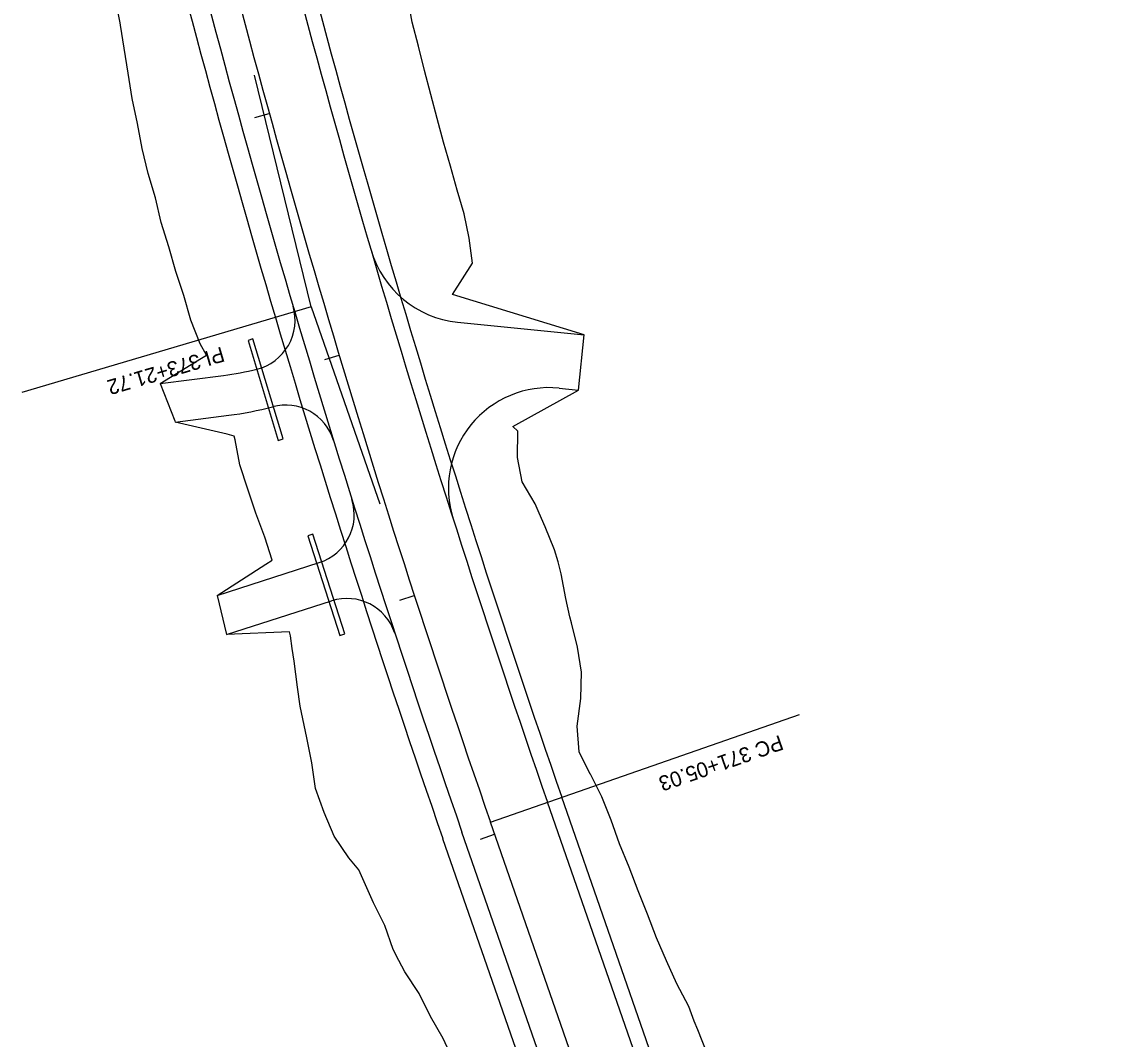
# Model space of a CAD drawing. Extents: x 948761 to 996004, y 1858548 to 1925175.
# Drawn here: x 960783.3 to 961214.2, y 1907979.6 to 1908383.8 of the extents above; entities that cross this region are included whole.
import ezdxf

# ---------------------------------------------------------------- set-up
doc = ezdxf.new("R2010")
doc.units = 0
for name, color, linetype in [('R_Drainage', 7, 'Continuous'), ('R_Horz Alg', 7, 'Continuous'), ('R_Horz Alg Annot', 7, 'Continuous'), ('R_Proposed Const Limits', 7, 'Continuous'), ('R_Proposed Road', 7, 'Continuous')]:
    doc.layers.add(name, color=color, linetype=linetype)

msp = doc.modelspace()

# ---------------------------------------------------------------- linework, layer by layer
at = {"layer": 'R_Drainage'}
for p, q in [((960875.16, 1908257.78), (960873.24, 1908257.2)), ((960887.15, 1908218.06), (960875.16, 1908257.78)), ((960873.24, 1908257.2), (960885.23, 1908217.49)), ((960885.23, 1908217.49), (960887.15, 1908218.06)), ((960898.93, 1908180.24), (960897.03, 1908179.63)), ((960911.66, 1908140.62), (960898.93, 1908180.24)), ((960897.03, 1908179.63), (960909.75, 1908140)), ((960909.75, 1908140), (960911.66, 1908140.62))]:
    msp.add_line(p, q, dxfattribs=at)
at = {"layer": 'R_Horz Alg'}
msp.add_line((961185.9, 1907443.82), (960969.55, 1908065.88), dxfattribs=at)
msp.add_arc((965298.84, 1909571.61), 4583.66, 193.76446, 199.17766, dxfattribs=at)
at = {"layer": 'R_Horz Alg Annot'}
for q in [(960875.81, 1908362.62), (960925.56, 1908192.35)]:
    msp.add_line((960898.37, 1908270.54), q, dxfattribs=at)
for points in [[(960875.9, 1908345.8), (960881.68, 1908347.4)], [(960898.37, 1908270.54), (960783.29, 1908236.52)], [(960903.69, 1908249.6), (960909.44, 1908251.33)], [(960933.58, 1908154.04), (960939.28, 1908155.89)], [(960969.55, 1908065.88), (961092.33, 1908108.59)], [(960965.53, 1908059.15), (960971.2, 1908061.13)]]:
    msp.add_lwpolyline(points, dxfattribs=at)
at = {"layer": 'R_Proposed Const Limits'}
for points in [[(960838.31, 1908240.11), (960854.69, 1908250.12), (960856.75, 1908251.37), (960854.25, 1908255.85), (960850.51, 1908265.29), (960847.7, 1908275.01), (960844.5, 1908284.61), (960841.81, 1908294.37), (960838.73, 1908304.01), (960836.46, 1908313.88), (960833.5, 1908323.55), (960831.22, 1908333.42), (960829.24, 1908343.36), (960827.15, 1908353.27), (960825.56, 1908363.32), (960823.94, 1908373.35), (960822.6, 1908382.45), (960822.46, 1908383.41), (960820.46, 1908393.33)], [(961006.76, 1908259.37), (960954.42, 1908275.47), (960962.45, 1908287.89), (960961.09, 1908297.77), (960959.12, 1908307.47), (960956.38, 1908316.94), (960953.66, 1908326.42), (960950.95, 1908335.9), (960948.31, 1908345.4), (960945.83, 1908354.95), (960943.36, 1908364.49), (960940.91, 1908374.05), (960938.49, 1908383.61), (960936.69, 1908393.33)], [(961004.77, 1908093.83), (961003.98, 1908104.03), (961005.41, 1908114.97), (961005.72, 1908125.51), (961004.1, 1908135.39), (961001.71, 1908145.01), (961001.12, 1908147.44), (960999.46, 1908154.67), (960997.67, 1908164.47), (960996.49, 1908169.31), (960996.48, 1908169.31), (960994.98, 1908173.98), (960991.33, 1908183.18), (960988.85, 1908188.6), (960987.34, 1908192.27), (960982.15, 1908200.98), (960980.34, 1908210.77), (960980.45, 1908221.15), (960978.4, 1908222.96), (961004.55, 1908237.48)], [(960860.9, 1908155.95), (960880.28, 1908168.34), (960882.78, 1908169.97), (960879.89, 1908179.11), (960876.36, 1908188.6), (960873.1, 1908198.18), (960869.92, 1908207.77), (960868.05, 1908217.78), (960867.77, 1908219.23), (960864.91, 1908219.94), (960844.3, 1908224.75)], [(960955.05, 1907970.81), (960950.7, 1907979.88), (960945.66, 1907988.72), (960941.25, 1907997.77), (960935.49, 1908006.36), (960933.19, 1908010.86), (960930.9, 1908015.35), (960927.64, 1908024.8), (960923.11, 1908033.81), (960917.26, 1908046.98), (960913.21, 1908051.72), (960907.4, 1908060.32), (960903.51, 1908069.7), (960900.09, 1908079.24), (960898.6, 1908089.43), (960896.54, 1908099.42), (960894.44, 1908109.4), (960893.97, 1908111.94), (960892.82, 1908119.52), (960891.56, 1908129.76), (960891.19, 1908132.31), (960890.82, 1908134.87), (960890.04, 1908139.9), (960889.75, 1908141.45), (960864.67, 1908140.35)], [(961055.61, 1907974.02), (961051.92, 1907983.32), (961050.48, 1907986.82), (961048.39, 1907992.68), (961043.63, 1908001.61), (961039.53, 1908010.78), (961035.53, 1908019.97), (961031.91, 1908029.3), (961028.22, 1908038.61), (961028.21, 1908038.64), (961024.59, 1908047.93), (961020.84, 1908057.21), (961017.46, 1908066.63), (961013.79, 1908075.94), (961011.8, 1908079.86), (961009.26, 1908084.9), (961009.21, 1908084.99), (961004.77, 1908093.83)]]:
    msp.add_lwpolyline(points, dxfattribs=at)
at = {"layer": 'R_Proposed Road'}
for p, q in [((960956.48, 1908264.45), (961006.76, 1908259.37)), ((961004.55, 1908237.48), (961006.76, 1908259.37)), ((960838.31, 1908240.11), (960863.51, 1908243.33)), ((960996.84, 1908238.26), (961004.55, 1908237.48)), ((960844.3, 1908224.75), (960865.54, 1908227.46)), ((960860.9, 1908155.95), (960901.53, 1908168.98)), ((960860.9, 1908155.95), (960864.67, 1908140.35)), ((960864.67, 1908140.35), (960906.42, 1908153.75)), ((961208.57, 1907451.7), (960992.22, 1908073.76)), ((961214.24, 1907453.67), (960997.88, 1908075.74)), ((961174.57, 1907439.88), (960958.21, 1908061.94)), ((961167.01, 1907437.25), (960950.66, 1908059.31))]:
    msp.add_line(p, q, dxfattribs=at)
msp.add_lwpolyline([(960838.31, 1908240.11), (960844.16, 1908225.34), (960844.3, 1908224.75)], dxfattribs=at)
for centre, radius, start, end in [((965298.84, 1909571.61), 4559.66, 193.76446, 199.17766), ((965298.84, 1909571.61), 4553.66, 193.76446, 199.17766), ((965298.84, 1909571.61), 4595.66, 193.76446, 199.17766), ((965298.84, 1909571.61), 4603.66, 193.76446, 199.17766), ((960960.5, 1908304.25), 40, 196.2847, 264.2289), ((960871.91, 1908265.21), 20, 283.8572, 16.4414), ((960848.68, 1908359.39), 117, 277.2843, 283.8572), ((960992.82, 1908198.46), 40, 84.2289, 197.687), ((960848.68, 1908359.39), 133, 277.2843, 284.9309), ((960888.1, 1908211.55), 20, 17.1372, 104.9309), ((960895.42, 1908188.03), 20, 287.7906, 17.443), ((960912.53, 1908134.71), 20, 18.1382, 107.7906)]:
    msp.add_arc(centre, radius, start, end, dxfattribs=at)

# ---------------------------------------------------------------- texts
at = {"layer": 'R_Horz Alg'}
msp.add_text('+', height=1, rotation=109.1777, dxfattribs=at).set_placement((960970.02, 1908066.04))
at = {"layer": 'R_Horz Alg Annot'}
for s, rotation, p in [('PI 373+21.72', 196.4711, (960862.74, 1908254.8)), ('PC 371+05.03', 199.1777, (961084.53, 1908100.58))]:
    msp.add_text(s, height=6, rotation=rotation, dxfattribs=at).set_placement(p)

doc.saveas('drawing.dxf')
